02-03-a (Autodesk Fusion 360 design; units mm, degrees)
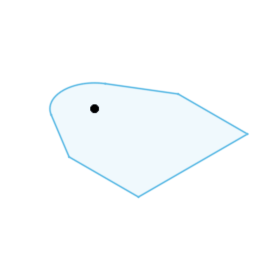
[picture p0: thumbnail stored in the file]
sketch "スケッチ" plane through (0, 0, 0) normal (0, 1, 0) x axis (1, 0, 0)
  line L1 (17.3949, 32.7065) -> (-9.8243, 16.2118)
  line L2 (58.999, 32.7065) -> (17.3949, 32.7065)
  line L3 (58.999, -32.7065) -> (58.999, 32.7065)
  line L4 (17.3949, -32.7065) -> (58.999, -32.7065)
  line L5 (-9.8243, -16.2118) -> (17.3949, -32.7065)
  arc A1 centre (0, 0) radius 18.9562 clockwise from (-9.8243, -16.2118) to (-9.8243, 16.2118)
  point P1 (0, 0)
  point P8 (0, 0)
  horizontal L2
  perpendicular L2 L3
  perpendicular L3 L4
  tangent L1 A1
  tangent L5 A1
  equal L1 L5
  equal L2 L4
  coincident P1 P8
